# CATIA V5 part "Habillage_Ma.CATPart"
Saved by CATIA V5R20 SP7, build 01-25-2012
Part number: Habillage_Ma
Publications: "Corps principal"
Bounding box of the stored display mesh (mm): x -4 to 0.5, y -83.041 to 2.897, z 16.859 to 28.496
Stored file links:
  F:\IAO\Catia\Habillage_Ma.CATPart
  F:\IAO\Catia\asandre.CATProduct
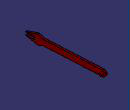
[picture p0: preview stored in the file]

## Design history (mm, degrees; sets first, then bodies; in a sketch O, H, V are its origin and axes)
Set1
  Plane1 "plan.-2": linked copy from another document
  Point1 "machoires.a": linked copy from another document
  Point2 "M": linked copy from another document
  Line1 "barre_Ma": linked copy from another document
Body1 (main body)
  Sketch1 "Bielle_Ma" on Plane1, origin (-2, 0, 0), H (0, 1, 0), V (0, 0, 1)
    construction line L1 (-58, 22.5) -> (0, 25.5)
    point P1 (-58, 22.5)
    point P2 (0, 25.5)
    line L2 (-64.0465, 25.1913) -> (-0.155, 28.496)
    line L3 (0.155, 22.504) -> (-63.7365, 19.1993)
    arc A1 centre (0, 25.5) radius 3 from (-0.155, 28.496) to (0.155, 22.504) cw
    point P3 (-64.0465, 25.1913)
    reference projected point E1 (-58, 22.5) from Point1
    reference projected point E2 (0, 25.5) from Point2
    axis line L4 (-58, 22.5) -> (0, 25.5)
    point P6 (-58, 22.5)
    point P7 (0, 25.5)
    reference projected point E3 (0, 25.5) from Point2
    reference projected point E4 (-58, 22.5) from Point1
    point P8 (-64.0465, 25.1913)
    line L5 (-64.0465, 25.1913) -> (-69.7831, 26.9494)
    point P9 (-69.7831, 26.9494)
    line L6 (-69.7831, 26.9494) -> (-83.0412, 22.6516)
    point P10 (-83.0412, 22.6516)
    line L7 (-83.0412, 22.6516) -> (-73.0545, 23.1681)
    point P11 (-73.0545, 23.1681)
    line L8 (-73.0545, 23.1681) -> (-72.977, 21.6701)
    point P12 (-72.977, 21.6701)
    reference projected line E5 (0, 25.5) -> (-67.9866, 21.9834) from Line1
    reference projected line E6 (0, 25.5) -> (-67.9866, 21.9834) from Line1
    point P13 (-72.9052, 20.2822)
    line L9 (-72.9052, 20.2822) -> (-72.977, 21.6701)
    point P14 (-82.8919, 19.7657)
    line L10 (-82.8919, 19.7657) -> (-72.9052, 20.2822)
    point P15 (-69.2612, 16.8587)
    line L11 (-69.2612, 16.8587) -> (-82.8919, 19.7657)
    line L12 (-63.7365, 19.1993) -> (-69.2612, 16.8587)
    point P16 (-72.977, 21.6701)
    reference projected line E7 (0, 25.5) -> (-67.9866, 21.9834) from Line1
    reference projected point E9 (-58, 22.5) from Point1
    distance L1 L2 = 3
    angle L5 L2 = 160
    distance L8 P10 = 10
    angle L7 L6 = 15
    distance P11 P12 = 1.5
    distance P3 P9 = 6
    distance P11 P9 = 5
    distance P12 E9 = 15
    tangency: A1 L2, A1 L3
    coincidence: P1 E1, P2 E2, P7 E3, P6 E4, P8 P3, P3 L5, P12 L8, P12 P16, L9 P12
    parallelism: E5 L7, L3 E7, L10 L4, L7 L4
    perpendicularity: L8 E6, L7 L8, L9 L10
    symmetry: P11 P13 L1, L8 L9 L1, P10 P14 L1, L7 L10 L1, P9 P15 L1, L6 L11 L1, L5 L12 L1
  Pad1 "Bielle_Ma": profile Sketch1, direction (-1, 0, 0), length 2
  Sketch2 "Pivot.M" on Plane1, origin (-2, 0, 0), H (0, 1, 0), V (0, 0, 1)
    circle A1 centre (0, 25.5) radius 1.5
    point P1 (0, 25.5)
    reference projected point E1 (0, 25.5) from Point2
    radius A1 = 1.5
    coincidence: P1 E1
  Pad2 "Pivot.M": profile Sketch2, direction (1, 0, 0), length 2.5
